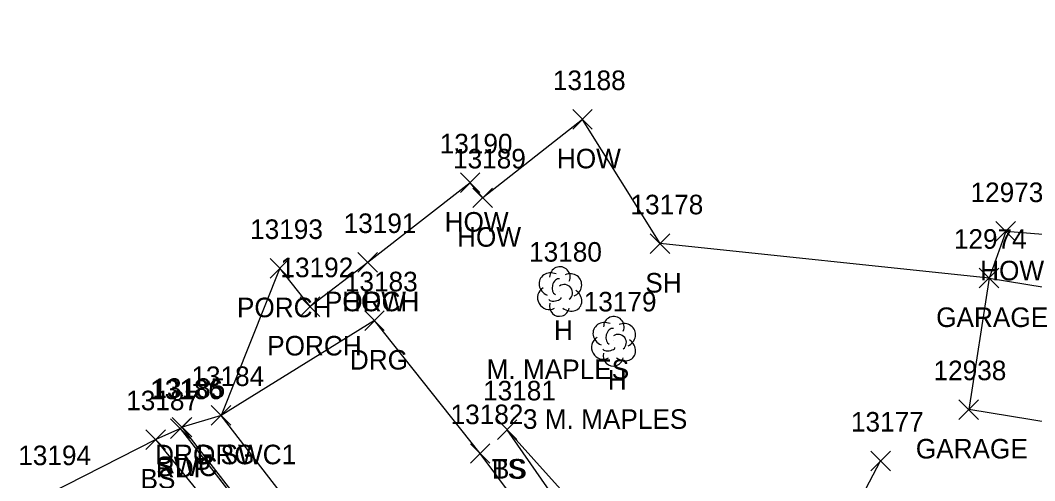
# Model space of a CAD drawing. Extents: x 1769141 to 1770911, y 735471 to 741449.
# Drawn here: x 1769790.9 to 1769894.5, y 741227.5 to 741274.6 of the extents above; entities that cross this region are included whole.
import ezdxf

# ---------------------------------------------------------------- set-up
doc = ezdxf.new("R2010")
doc.units = 0
for name, color, linetype in [('L_A', 7, 'Continuous'), ('L_C', 7, 'Continuous'), ('L_I', 7, 'Continuous'), ('L_TIC', 7, 'Continuous'), ('LBC', 7, 'Continuous'), ('LBF', 7, 'Continuous'), ('LELB', 7, 'Continuous'), ('LSOGP', 7, 'Continuous'), ('LTD', 7, 'Continuous'), ('P_A', 7, 'Continuous'), ('P_I', 7, 'Continuous'), ('P_TIC', 7, 'Continuous'), ('PET', 7, 'Continuous'), ('R_A', 7, 'Continuous'), ('R_I', 7, 'Continuous'), ('R_TIC', 7, 'Continuous'), ('RDG', 7, 'Continuous'), ('RSW', 7, 'Continuous')]:
    doc.layers.add(name, color=color, linetype=linetype)

msp = doc.modelspace()

# ---------------------------------------------------------------- linework, layer by layer
at = {"layer": 'L_TIC'}
for points in [[(1769847.35, 741263.46), (1769849.35, 741265.46)], [(1769849.35, 741263.46), (1769847.35, 741265.46)], [(1769835.87, 741256.99), (1769837.87, 741258.99)], [(1769837.87, 741256.99), (1769835.87, 741258.99)], [(1769837.15, 741255.45), (1769839.15, 741257.45)], [(1769839.15, 741255.45), (1769837.15, 741257.45)], [(1769890.58, 741252.01), (1769892.58, 741254.01)], [(1769892.58, 741252.01), (1769890.58, 741254.01)], [(1769855.27, 741250.76), (1769857.27, 741252.76)], [(1769857.27, 741250.76), (1769855.27, 741252.76)], [(1769825.4, 741248.85), (1769827.4, 741250.85)], [(1769827.4, 741248.85), (1769825.4, 741250.85)], [(1769825.4, 741248.85), (1769827.4, 741250.85)], [(1769827.4, 741248.85), (1769825.4, 741250.85)], [(1769816.42, 741248.24), (1769818.42, 741250.24)], [(1769818.42, 741248.24), (1769816.42, 741250.24)], [(1769888.88, 741247.24), (1769890.88, 741249.24)], [(1769890.88, 741247.24), (1769888.88, 741249.24)], [(1769888.88, 741247.24), (1769890.88, 741249.24)], [(1769890.88, 741247.24), (1769888.88, 741249.24)], [(1769819.51, 741244.33), (1769821.51, 741246.33)], [(1769821.51, 741244.33), (1769819.51, 741246.33)], [(1769886.8, 741233.8), (1769888.8, 741235.8)], [(1769888.8, 741233.8), (1769886.8, 741235.8)], [(1769886.8, 741233.8), (1769888.8, 741235.8)], [(1769888.8, 741233.8), (1769886.8, 741235.8)], [(1769839.65, 741231.74), (1769841.65, 741233.74)], [(1769841.65, 741231.74), (1769839.65, 741233.74)], [(1769839.65, 741231.74), (1769841.65, 741233.74)], [(1769841.65, 741231.74), (1769839.65, 741233.74)], [(1769803.75, 741230.73), (1769805.75, 741232.73)], [(1769805.75, 741230.73), (1769803.75, 741232.73)], [(1769877.8, 741228.55), (1769879.8, 741230.55)], [(1769879.8, 741228.55), (1769877.8, 741230.55)]]:
    msp.add_lwpolyline(points, dxfattribs=at)
at = {"layer": 'LBC'}
for points in [[(1769947.2, 741302.57), (1769958.21, 741301.32), (1769957.54, 741294.95), (1769957.01, 741290.28), (1769955.5, 741276.77), (1769915.32, 741281.14), (1769911.76, 741281.4), (1769909.98, 741266.71), (1769914.33, 741266.58), (1769913.44, 741254.09), (1769913.19, 741251.19), (1769912.43, 741251.34), (1769912.2, 741251.32), (1769891.58, 741253.01)], [(1769848.35, 741264.46), (1769838.15, 741256.45), (1769836.87, 741257.99), (1769826.4, 741249.85)], [(1769889.88, 741248.24), (1769910.91, 741244.8), (1769908.79, 741231.38), (1769887.8, 741234.8)], [(1769889.88, 741248.24), (1769887.8, 741234.8)]]:
    msp.add_lwpolyline(points, dxfattribs=at)
at = {"layer": 'LBF'}
msp.add_lwpolyline([(1769826.4, 741249.85), (1769820.51, 741245.33), (1769817.42, 741249.24)], dxfattribs=at)
at = {"layer": 'LELB'}
for points in [[(1769846.43, 741192.29), (1769858.48, 741207.07), (1769840.65, 741232.74)], [(1769851.24, 741188.66), (1769849.68, 741191.2), (1769863.36, 741207.44), (1769840.65, 741232.74)], [(1769870.79, 741153.4), (1769849.53, 741177.81), (1769829.95, 741200.84), (1769804.75, 741231.73)], [(1769851.24, 741188.66), (1769866.4, 741205.87), (1769878.8, 741229.55)]]:
    msp.add_lwpolyline(points, dxfattribs=at)
at = {"layer": 'LSOGP'}
msp.add_lwpolyline([(1769912.2, 741251.32), (1769891.58, 741253.01), (1769889.88, 741248.24), (1769856.27, 741251.76), (1769848.35, 741264.46), (1769838.15, 741256.45), (1769836.87, 741257.99), (1769826.4, 741249.85), (1769820.51, 741245.33), (1769817.42, 741249.24), (1769811.42, 741234.21), (1769807.44, 741233), (1769807.26, 741232.86), (1769804.75, 741231.73), (1769793.73, 741226.12)], dxfattribs=at)
at = {"layer": 'LTD'}
for p, q in [((1769846, 741246.92), (1769846, 741246.92)), ((1769846, 741246.92), (1769846, 741246.92)), ((1769851.5, 741241.83), (1769851.5, 741241.83)), ((1769851.5, 741241.83), (1769851.5, 741241.83))]:
    msp.add_line(p, q, dxfattribs=at)
for centre in [(1769846.04, 741248.35), (1769851.55, 741243.26)]:
    msp.add_arc(centre, 1.05, 335.5272, 180.9563, dxfattribs=at)
for centre, major_axis, ratio, start_param, end_param in [((1769845.2, 741247.58), (1.21, -0.51), 0.895232, 1.570796, 4.712389), ((1769847.04, 741247.5), (-1.14, -0.48), 0.949671, 1.570796, 4.712389), ((1769845.79, 741247.37), (-0.208, -0.792), 0.645439, 3.141593, 6.283185), ((1769846.5, 741246.75), (-0.5, 0.667), 0.989748, 3.141593, 6.283185), ((1769844.91, 741246.21), (0.58, -1.04), 0.959034, 3.141593, 6.283185), ((1769847, 741246.08), (-1.09, 0.79), 0.841452, 1.570796, 4.712389), ((1769846, 741245.42), (0.26, 1.06), 0.942809, 1.570796, 4.712389), ((1769845.54, 741246.17), (-0.625, -0.083), 0.423636, 0, 3.141593), ((1769850.71, 741242.5), (1.21, -0.51), 0.895232, 1.570796, 4.712389), ((1769852.54, 741242.41), (-1.14, -0.48), 0.949671, 1.570796, 4.712389), ((1769851.29, 741242.29), (-0.208, -0.792), 0.645439, 3.141593, 6.283185), ((1769852, 741241.66), (-0.5, 0.667), 0.989748, 3.141593, 6.283185), ((1769850.42, 741241.12), (0.58, -1.04), 0.959034, 3.141593, 6.283185), ((1769852.5, 741241), (-1.09, 0.79), 0.841452, 1.570796, 4.712389), ((1769851.5, 741240.33), (0.26, 1.06), 0.942809, 1.570796, 4.712389), ((1769851.04, 741241.08), (-0.625, -0.083), 0.423636, 0, 3.141593)]:
    msp.add_ellipse(centre, major_axis=major_axis, ratio=ratio, start_param=start_param, end_param=end_param, dxfattribs=at)
at = {"layer": 'P_TIC'}
for points in [[(1769806.26, 741231.86), (1769808.26, 741233.86)], [(1769808.26, 741231.86), (1769806.26, 741233.86)]]:
    msp.add_lwpolyline(points, dxfattribs=at)
at = {"layer": 'PET'}
msp.add_lwpolyline([(1769991.23, 741290.01), (1769987.19, 741269.35), (1769986.03, 741257.36), (1769981.29, 741229.12), (1769977.72, 741213.51), (1769975.81, 741205.96), (1769969.15, 741183.59), (1769965.01, 741170.54), (1769960.16, 741153.99), (1769952.24, 741138.6), (1769942.53, 741130.28), (1769939.29, 741128.63), (1769934.36, 741126.79), (1769926.37, 741125.5), (1769918.11, 741126.67), (1769910.46, 741128.98), (1769895.97, 741135.78), (1769882.33, 741145.09), (1769876.36, 741150.21), (1769873.31, 741153.13), (1769873.55, 741153.49), (1769849.64, 741178.94), (1769831.32, 741201.9), (1769807.26, 741232.86)], dxfattribs=at)
at = {"layer": 'R_TIC'}
for points in [[(1769826.1, 741242.89), (1769828.1, 741244.89)], [(1769828.1, 741242.89), (1769826.1, 741244.89)], [(1769810.42, 741233.21), (1769812.42, 741235.21)], [(1769812.42, 741233.21), (1769810.42, 741235.21)], [(1769810.42, 741233.21), (1769812.42, 741235.21)], [(1769812.42, 741233.21), (1769810.42, 741235.21)], [(1769806.44, 741232), (1769808.44, 741234)], [(1769808.44, 741232), (1769806.44, 741234)], [(1769836.89, 741229.31), (1769838.89, 741231.31)], [(1769838.89, 741229.31), (1769836.89, 741231.31)]]:
    msp.add_lwpolyline(points, dxfattribs=at)
at = {"layer": 'RDG'}
msp.add_lwpolyline([(1769842.59, 741193.87), (1769855.22, 741207.09), (1769837.89, 741230.31), (1769827.1, 741243.89), (1769811.42, 741234.21)], dxfattribs=at)
at = {"layer": 'RSW'}
for points in [[(1769960.29, 741289.92), (1769976.56, 741287.94), (1769973.97, 741269.93), (1769972.42, 741259.76), (1769968.56, 741230.61), (1769968.11, 741227.71), (1769966.71, 741218.84), (1769964.63, 741204.16), (1769961.36, 741184.32), (1769958.49, 741172.85), (1769952.69, 741157.87), (1769944.84, 741143.76), (1769936.84, 741134.72), (1769932.32, 741131.39), (1769925.79, 741130.28), (1769919.63, 741131.08), (1769912.21, 741133.23), (1769898.13, 741139.61), (1769885.36, 741148.58), (1769879.35, 741153.54), (1769876.61, 741156.24), (1769851.48, 741183.14), (1769842.59, 741193.87), (1769811.42, 741234.21)], [(1769873.65, 741153.62), (1769848.49, 741180.66), (1769831.48, 741202.02), (1769807.44, 741233)]]:
    msp.add_lwpolyline(points, dxfattribs=at)

# ---------------------------------------------------------------- texts
at = {"layer": 'L_A'}
for s, p in [('HOW', (1769845.73, 741259.46)), ('HOW', (1769834.26, 741252.99)), ('HOW', (1769835.53, 741251.45)), ('HOW', (1769888.97, 741248.01)), ('SH', (1769854.76, 741246.76)), ('PORCH', (1769822.02, 741244.85)), ('HOW', (1769823.78, 741244.85)), ('PORCH', (1769813.04, 741244.24)), ('GARAGE', (1769884.48, 741243.24)), ('GARAGE', (1769884.48, 741243.24)), ('H', (1769845.43, 741241.92)), ('PORCH', (1769816.13, 741240.33)), ('H', (1769850.93, 741236.83)), ('GARAGE', (1769882.4, 741229.8)), ('GARAGE', (1769882.4, 741229.8)), ('TS', (1769839.06, 741227.74)), ('BS', (1769839.09, 741227.74)), ('BS', (1769803.19, 741226.73))]:
    msp.add_text(s, height=2, dxfattribs=at).set_placement(p)
at = {"layer": 'L_C'}
for s, p in [('M. MAPLES', (1769838.55, 741237.92)), ('3 M. MAPLES', (1769842.26, 741232.83))]:
    msp.add_text(s, height=2, dxfattribs=at).set_placement(p)
at = {"layer": 'L_I'}
for s, p in [('13188', (1769845.32, 741267.46)), ('13190', (1769833.76, 741260.99)), ('13189', (1769835.12, 741259.45)), ('12973', (1769887.99, 741256.01)), ('13178', (1769853.25, 741254.76)), ('13191', (1769823.94, 741252.85)), ('13191', (1769823.94, 741252.85)), ('13193', (1769814.39, 741252.24)), ('12974', (1769886.29, 741251.24)), ('12974', (1769886.29, 741251.24)), ('13180', (1769842.89, 741249.92)), ('13192', (1769817.49, 741248.33)), ('13179', (1769848.47, 741244.83)), ('12938', (1769884.21, 741237.8)), ('12938', (1769884.21, 741237.8)), ('13181', (1769838.19, 741235.74)), ('13181', (1769838.19, 741235.74)), ('13187', (1769801.73, 741234.73)), ('13177', (1769875.77, 741232.55))]:
    msp.add_text(s, height=2, dxfattribs=at).set_placement(p)
at = {"layer": 'P_A'}
msp.add_text('RDP', height=2, dxfattribs=at).set_placement((1769804.75, 741227.86))
at = {"layer": 'P_I'}
for s, p in [('13186', (1769804.18, 741235.86)), ('13194', (1769790.7, 741229.12))]:
    msp.add_text(s, height=2, dxfattribs=at).set_placement(p)
at = {"layer": 'R_A'}
for s, p in [('DRG', (1769824.58, 741238.89)), ('DRG SWC1', (1769804.68, 741229.21)), ('DRG', (1769808.91, 741229.21)), ('SWC', (1769804.8, 741228))]:
    msp.add_text(s, height=2, dxfattribs=at).set_placement(p)
at = {"layer": 'R_I'}
for s, p in [('13183', (1769824.07, 741246.89)), ('13184', (1769808.39, 741237.21)), ('13184', (1769808.39, 741237.21)), ('13185', (1769804.41, 741236)), ('13182', (1769834.87, 741233.31))]:
    msp.add_text(s, height=2, dxfattribs=at).set_placement(p)

doc.saveas('drawing.dxf')
